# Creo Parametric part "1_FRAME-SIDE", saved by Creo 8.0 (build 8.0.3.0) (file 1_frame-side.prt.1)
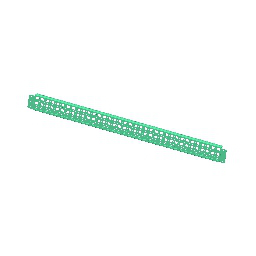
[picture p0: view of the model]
Units: millimeter Newton Second (mmNs); MM, TONNE, SECS

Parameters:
  SMT_DFLT_BEND_REL_LENGTH_TYPE = "Through All"

Other parameters: SMT_UPDATE_BEND_ALLOW_INFO, SMT_THICKNESS, SMT_PART_BEND_ALLOWANCE_FACTOR, SMT_DFLT_BEND_RADIUS, SMT_DFLT_BEND_ANGLE, SMT_DFLT_CRNR_REL_WIDTH, SMT_DFLT_CRNR_REL_DEPTH, SMT_DFLT_BEND_REL_WIDTH, SMT_DFLT_BEND_REL_DEPTH, SMT_DFLT_BEND_REL_LENGTH, SMT_DFLT_BEND_REL_ANGLE, SMT_GAP, SMT_DFLT_EDGE_TREA_WIDTH, SMT_DFLT_MITER_CUT_WIDTH, SMT_DFLT_MITER_CUT_OFFSET, D124

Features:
  1. datum plane "RIGHT"
  2. datum plane "TOP"
  3. datum plane "FRONT"
  4. coordinate system
  5. pattern
  6. cut
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
Layers: 0_ALL_AXIS, 0_ALL_CSYS, 0_ALL_CURVES, 0_ALL_PLANES, 0_ALL_POINTS, 0_ALL_SURFS, FRAME-SIDE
